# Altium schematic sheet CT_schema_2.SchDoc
size 207 x 170 mm
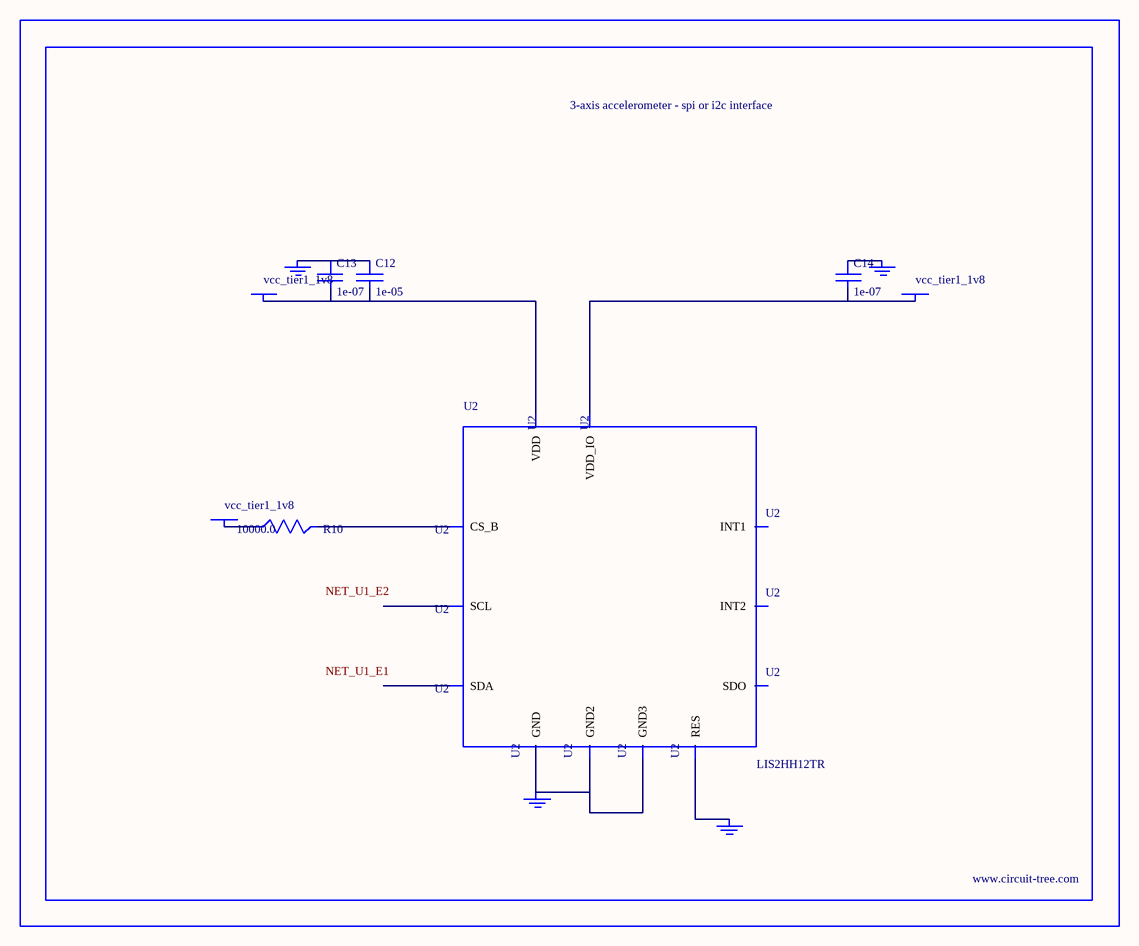
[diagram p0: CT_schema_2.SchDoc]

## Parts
BORDER1  (no value)
C12  1e-05  [C0805]
C13  1e-07  [C0402]
C14  1e-07  [C0402]
GND_INSTANCE_1_0  (no value)
GND_INSTANCE_1_1  (no value)
GND_INSTANCE_1_2  (no value)
GND_INSTANCE_1_3  (no value)
POWER_INSTANCE_1_0  vcc_tier1_1v8
POWER_INSTANCE_1_1  vcc_tier1_1v8
POWER_INSTANCE_1_2  vcc_tier1_1v8
R10  10000.0  [R0603]
U2  LIS2HH12TR  [LGA-12]

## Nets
NetC12_1: C12.1 C13.1 GND_INSTANCE_1_1.0(GND)
NetC12_2: C12.2 C13.2 POWER_INSTANCE_1_1.0(PWR) U2.9(VDD)
NetC14_1: C14.1 GND_INSTANCE_1_2.0(GND)
NetC14_2: C14.2 POWER_INSTANCE_1_2.0(PWR) U2.10(VDD_IO)
NetGND_INSTANCE_1_0_0: GND_INSTANCE_1_0.0(GND) U2.5(RES)
NetGND_INSTANCE_1_3_0: GND_INSTANCE_1_3.0(GND) U2.6(GND) U2.7(GND2) U2.8(GND3)
NetPOWER_INSTANCE_1_0_0: POWER_INSTANCE_1_0.0(PWR) R10.1
NetR10_2: R10.2 U2.2(CS_B)

Not connected (* = marked no-connect by the designer): U2 1(SCL) 3(SDO) 4(SDA) 11(INT2) 12(INT1)

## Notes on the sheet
- Labels drawn without touching a wire or pin: NET_U1_E1, NET_U1_E2

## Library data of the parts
BORDER1 = BORDER_PAGE1
C12 = C0805C106K8RACTU
C13 C14 = C0402C104K3RACTU
GND_INSTANCE_1_0-GND_INSTANCE_1_3 = GND
POWER_INSTANCE_1_0-POWER_INSTANCE_1_2 = PWR
R10 = RC0603JR-0710KL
